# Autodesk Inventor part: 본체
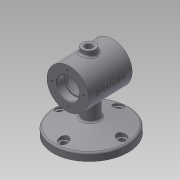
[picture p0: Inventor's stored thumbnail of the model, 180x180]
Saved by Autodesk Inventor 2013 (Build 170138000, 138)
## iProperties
Created: 2018-12
Part Number: 본체
Material: 일반
Document SubType Name: Modeling
Designer: Administrator
Density: 1 g/cm^3
Author: Administrator
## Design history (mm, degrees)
sketch "스케치2"
  geometry: C1 r 30 at (0, 0); 1 further point
  constraints: 1 centre point, 1 coincident
  dimensions: "d3" = 60 diameter of C1
extrude "돌출1" new body sketch "스케치2" stored distance "d5" = 70; taper "d6" = 0 deg
sketch "스케치3"
  geometry: C1 r 30 at (0, 0) reference; 1 further point
  constraints: 1 coincident
hole "구멍1" sketch "스케치3" at (0, 0) diameter "d7" = 28; stored, may be unused: countersink angle "d11" = 90 deg, drill point angle "d13" = 0 deg; dims "d8" = 6, "d9" = 32, "d10" = 12, "d12" = 15
sketch "스케치5"
  geometry: C1 r 14 at (0, 0) reference; C2 r 25 at (0, 0)
  constraints: 1 centre point, 1 coincident
  dimensions: "d18" = 50 diameter of C2
extrude "돌출3" cut sketch "스케치5" distance "d20" = 40; taper "d21" = 0 deg
sketch "스케치6" dims "d22" = 46
  geometry: C1 r 16 at (0, 0) reference; C2 r 30 at (0, 0) reference; 2 further points
  constraints: 1 coincident, 1 vertical alignment, 2 other
  dimensions: "d25" = 23 distance of point (0, 23) C1.centre
hole "구멍2" sketch "스케치6" at (0, 23) diameter "d26" = 3.242; stored, may be unused: countersink angle "d30" = 90 deg, drill point angle "d32" = 118 deg; dims "d27" = 8, "d28" = 32, "d29" = 12, "d31" = 10
node "작업 평면1"
sketch "스케치7"
  geometry: C1 r 10 at (0, 0); 1 further point
  constraints: 1 centre point, 1 coincident
  dimensions: "d37" = 20 diameter of C1
extrude "돌출4" join sketch "스케치7" stored distance "d39" = 40; taper "d40" = 0 deg
sketch "스케치9"
  geometry: C1 r 10 at (0, 0) reference; C2 r 5 at (0, 0)
  constraints: 1 centre point, 1 coincident
  dimensions: "d41" = 10 diameter of C2
extrude "돌출5" cut sketch "스케치9" distance "d43" = 40; taper "d44" = 0 deg
node "작업 평면2"
sketch "스케치10"
  geometry: C1 r 55 at (0, 0); 1 further point
  constraints: 1 centre point, 1 coincident
  dimensions: "d46" = 110 diameter of C1
extrude "돌출6" join sketch "스케치10" distance "d48" = 11; taper "d49" = 0 deg
sketch "스케치15"
  geometry: C1 r 55 at (0, 0) reference; A1 r 44 centre (0, 0) between (0, 44) and (44, 0); 2 further points
  constraints: 4 point on circle, 1 centre point, 1 coincident
  dimensions: "d69" = 88 diameter of A1
extrude "돌출8" join sketch "스케치15" distance "d54" = 15; taper "d55" = -75 deg
sketch "스케치16"
  geometry: C1 r 55 at (0, 0) reference; C2 r 12 at (0, 0)
  constraints: 1 centre point, 1 coincident
  dimensions: "d56" = 24 diameter of C2
extrude "돌출9" join sketch "스케치16" stored distance "d58" = 15; taper "d59" = 0 deg
sketch "스케치17"
  geometry: C1 r 55 at (0, 0) reference; A1 r 44 centre (0, 0) between (0, 44) and (44, 0); 2 further points
  constraints: 4 point on circle, 1 centre point, 1 coincident
  dimensions: "d60" = 88 diameter of A1
hole "구멍3" sketch "스케치17" at (0, 44), (44, 0), (0, -44), (-44, 0) diameter "d62" = 9; stored, may be unused: countersink angle "d66" = 90 deg, drill point angle "d68" = 118 deg; dims "d63" = 8, "d64" = 32, "d65" = 12, "d67" = 10
node "작업 평면4"
sketch "스케치18" dims "d73" = 88
  geometry: C1 r 7 at (0, 44); 2 further points
  constraints: 1 centre point, 1 coincident, 1 vertical alignment, 2 other
  dimensions: "d75" = 14 diameter of C1
extrude "돌출10" cut sketch "스케치18" distance "d76" = 15; taper "d77" = 0 deg
chamfer "모따기1" distance "d81" = 1; stored, may be unused: second distance "d82" = 2, angle "d83" = 45 deg
fillet "모깎기1" dims "d84" = 0.3
fillet "모깎기2" dims "d85" = 3
fillet "모깎기3" dims "d86" = 3
fillet "모깎기4" dims "d87" = 3
fillet "모깎기5" dims "d88" = 3
fillet "모깎기6" dims "d89" = 1
node "작업 평면5"
sketch "스케치20"
  geometry: L1 (30, 35)-(-30, 35) reference; L2 (30, -35)-(30, 35) reference; 2 further points
  constraints: 1 other
  dimensions: "d93" = 35 distance from line of L1 point (0, 0); "d94" = 30 distance from line of L2 point (0, 0)
feature "엠보싱1" sketch "스케치20" dims "d95" = 0.5, "d96" = 0
node "솔리드1"
mirror "대칭1"
pattern_circular "원형 패턴1" dims angle "d34" = 360 deg
mirror "대칭2"
pattern_circular "원형 패턴2" dims angle "d79" = 360 deg
other parameters: "d36" = 37, "d45" = -75, "d72" = -65
